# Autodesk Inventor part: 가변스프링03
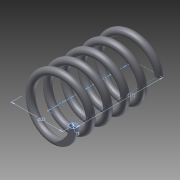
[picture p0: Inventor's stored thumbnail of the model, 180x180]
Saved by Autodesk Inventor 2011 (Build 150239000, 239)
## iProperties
Created: 2015-05
Part Number: 가변스프링03
Material: 탄소강
Document SubType Name: Modeling
Designer: Administrator
Mass: 18.8475 g
Surface Area: 32.4803 cm^2
Volume: 2.39485 cm^3
Density: 7.87 g/cm^3
Author: Administrator
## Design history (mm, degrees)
sketch "스케치1"
  geometry: L1 (0, 0)-(11, 0); L2 (11, 0)-(11, 36.411); L3 (11, 36.411)-(0, 36.411); L4 (0, 36.411)-(0, 0); C1 r 1.5 at (11, 0); 1 further point
  constraints: 8 end point, 2 coincident, 2 parallel, 1 centre point, 1 horizontal, 1 perpendicular
  dimensions: "d0" = 36.4112 distance of L1.end L2.end (derived); "d1" = 22 diameter of L2 L4; "d2" = 3 diameter of C1
feature "코일1" sketch "스케치1" pitch "d3" = 10; turns "d5" = 5; dims "d4" = 36.4112 (= d0), "d6" = 0, angle "d7" = 90 deg, angle "d8" = 90 deg, "d9" = 0, "d10" = 0
sketch "스케치2"
  geometry: L1 (-12.5, 0)-(-9.5, 0) reference; 1 further point
  constraints: 1 horizontal alignment
extrude "돌출1" cut sketch "스케치2" stored distance "d11" = 10; taper "d12" = 0 deg
node "작업 평면1"
sketch "스케치3"
  geometry: L1 (1.5, 0)-(-1.5, 0) reference; 1 further point
  constraints: 1 horizontal alignment
extrude "돌출2" cut sketch "스케치3" stored distance "d13" = 10; taper "d14" = 0 deg
node "솔리드1"
node "절단 모서리 투영1"
node "절단 모서리 투영2"
